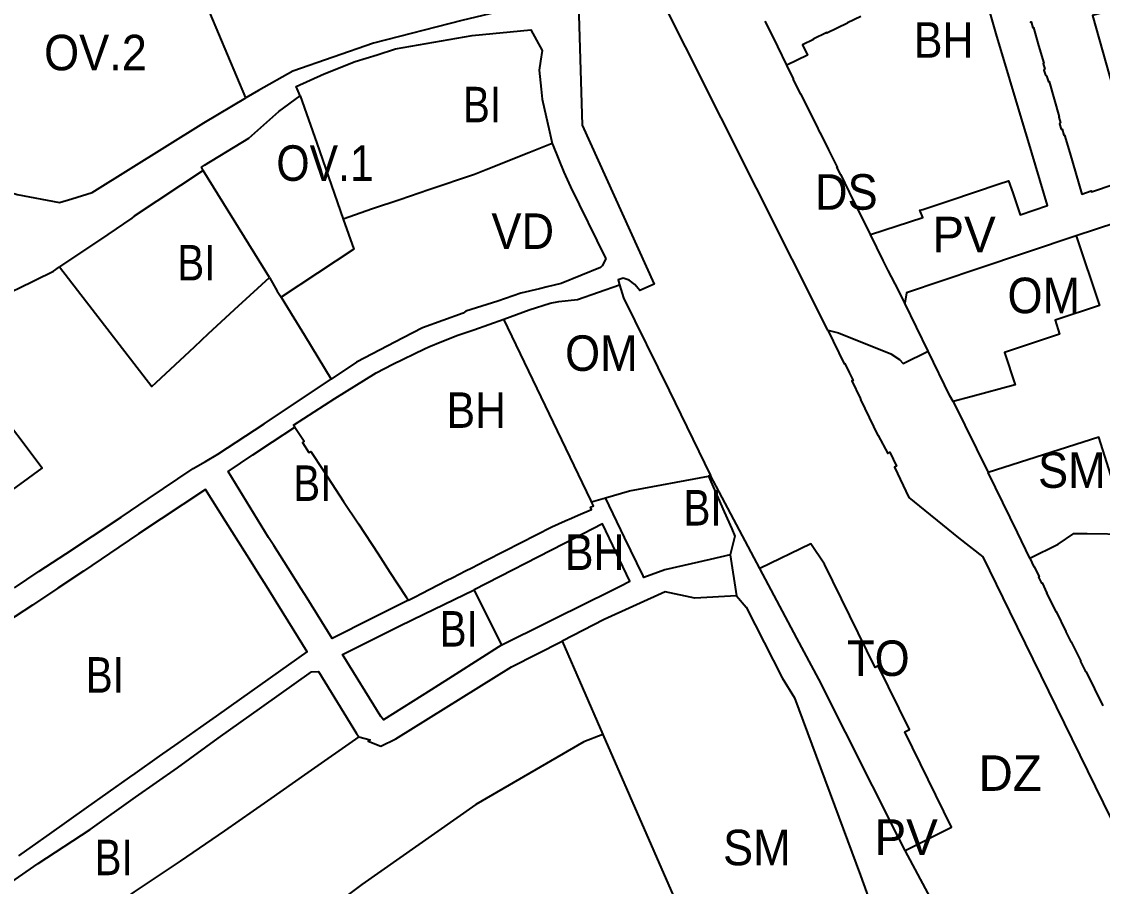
# Model space of a CAD drawing. Extents: x -650451 to -642268, y -1075216 to -1066610.
# Drawn here: x -648055.9 to -647599.3, y -1071003.9 to -1070638.7 of the extents above; entities that cross this region are included whole.
import ezdxf

# ---------------------------------------------------------------- set-up
doc = ezdxf.new("R2010")
doc.units = 0
doc.header["$LTSCALE"] = 6
doc.layers.add('1', color=7, linetype='Continuous', lineweight=35)
doc.layers.add('2', color=7, linetype='Continuous')
doc.layers.add('3', color=7, linetype='Continuous')

msp = doc.modelspace()

# ---------------------------------------------------------------- linework, layer by layer
at = {"layer": '1'}
for p, q in [((-647951.11, -1070746.78), (-647979.17, -1070701.65)), ((-647672.865, -1070777.891), (-647682.67, -1070757.67)), ((-647662.26, -1070799.23), (-647647.571, -1070829.133)), ((-647764.84, -1070830.47), (-647765.72, -1070830.64)), ((-647815.09, -1070841.49), (-647809.12, -1070839.89)), ((-647756.45, -1070863.95), (-647753.81, -1070881.3)), ((-647852.97, -1070901.96), (-647864.71, -1070878.74)), ((-647827.527, -1070900.351), (-647810.243, -1070939.825)), ((-647810.243, -1070939.825), (-647765.408, -1071042.223))]:
    msp.add_line(p, q, dxfattribs=at)
for points in [[(-647884.92, -1070338.99), (-647886.21, -1070365.54), (-647887.07, -1070416.41), (-647878.96, -1070462.33), (-647864.39, -1070538.27), (-647847.43, -1070592.87), (-647838.01, -1070623.65), (-647823.823, -1070616.697), (-647819.04, -1070625.82), (-647820.78, -1070626.64), (-647818.97, -1070682.49), (-647788.61, -1070749.59), (-647794.72, -1070752.32), (-647796.81, -1070749.77), (-647799.17, -1070747.87), (-647801.72, -1070747.13), (-647803.86, -1070747.73), (-647803.27, -1070749.84)], [(-647879.89, -1070513.91), (-647874.57, -1070543.74), (-647874.57, -1070544.88), (-647875.18, -1070545.86), (-647875.88, -1070546.28), (-647875.79, -1070546.93), (-647875.64, -1070547.77), (-647874.97, -1070551.71), (-647874.48, -1070554.33), (-647872.39, -1070554.51), (-647871.15, -1070555.05), (-647870.17, -1070556.03), (-647869.25, -1070556.63), (-647848.14, -1070626.09), (-647847.8, -1070628.31), (-647849.67, -1070630.94), (-647855.03, -1070634.7), (-647869.87, -1070638.25), (-647907.21, -1070647.84), (-647941.33, -1070659.67), (-647955.81, -1070667.9), (-647961.11, -1070670.91)], [(-647961.11, -1070670.91), (-647980.2, -1070625.7), (-647984.03, -1070585.46)], [(-647715.3, -1070769.09), (-647790.4, -1070619.27), (-647792.4, -1070613.99)], [(-647697.19, -1070728.71), (-647675.18, -1070721.4), (-647676.32, -1070718.44), (-647675.08, -1070718.03), (-647663.76, -1070714.27), (-647642.89, -1070707.32), (-647638.89, -1070706.02), (-647637.16, -1070711.08), (-647633.97, -1070720.39), (-647622.42, -1070716.46), (-647630.62, -1070688.97), (-647632.63, -1070682.45), (-647644.14, -1070643.84), (-647648.1, -1070630.11)], [(-647701.31, -1070636.54), (-647706.97, -1070639.28), (-647706.92, -1070639.43), (-647711.25, -1070641.47), (-647715.62, -1070643.56), (-647715.68, -1070643.41), (-647721.4, -1070646.19), (-647721.35, -1070646.32), (-647725.98, -1070648.59), (-647723.91, -1070652.88), (-647732.61, -1070657.08)], [(-647598.3, -1070634.71), (-647603.37, -1070636.19), (-647593.48, -1070671.67), (-647553.95, -1070659.71)], [(-647732.61, -1070657.08), (-647736.4, -1070649.31), (-647740.59, -1070640.7), (-647741.7, -1070638.5)], [(-647629.93, -1070638.72), (-647629.59, -1070638.94), (-647629.41, -1070638.87), (-647628.67, -1070641.34), (-647628.41, -1070641.25), (-647626.19, -1070648.79), (-647624.04, -1070656.27), (-647624.32, -1070656.37), (-647623.61, -1070658.84), (-647623.84, -1070658.92), (-647623.94, -1070659.3), (-647623.36, -1070661.41), (-647623.03, -1070661.67), (-647622.83, -1070661.6), (-647622.06, -1070664.18), (-647621.78, -1070664.08), (-647619.6, -1070671.54), (-647617.45, -1070678.98), (-647617.73, -1070679.09), (-647617.01, -1070681.56), (-647617.24, -1070681.65), (-647617.37, -1070681.97), (-647616.72, -1070684.14), (-647616.47, -1070684.33), (-647616.22, -1070684.23), (-647615.48, -1070686.75), (-647615.21, -1070686.65), (-647612.98, -1070694.17), (-647607.96, -1070711.55), (-647604.05, -1070710.22), (-647603.9, -1070710.66), (-647594.26, -1070707.45)], [(-647938.2, -1070670.05), (-647939.82, -1070666.19), (-647928.03, -1070660.74), (-647914.94, -1070655.62), (-647905.7, -1070652.72), (-647897.91, -1070650.27), (-647865.49, -1070644.56), (-647840.71, -1070642.28), (-647835.98, -1070650.97), (-647836.7, -1070655.5), (-647837.27, -1070659.18), (-647836.41, -1070667.24), (-647835.96, -1070671.43), (-647832.86, -1070685.08), (-647831.69, -1070690.25)], [(-647697.19, -1070728.71), (-647706.03, -1070710.73), (-647709.63, -1070703.43), (-647709.81, -1070703.52), (-647711.41, -1070700.27), (-647711.22, -1070700.17), (-647714.83, -1070692.9), (-647718.4, -1070685.67), (-647718.46, -1070685.698), (-647720.094, -1070682.395), (-647720.01, -1070682.36), (-647723.69, -1070675.2), (-647726.54, -1070669.36), (-647726.67, -1070669.43), (-647729.88, -1070663.01), (-647729.74, -1070662.95), (-647732.61, -1070657.08)], [(-648098.637, -1070659.682), (-648089.82, -1070676.22), (-648073.56, -1070706.71), (-648073.25, -1070706.87), (-648062.7, -1070710.16), (-648057.8, -1070711.7), (-648039.79, -1070715.13), (-648034.59, -1070713.53), (-648034.6, -1070713.538), (-648026.1, -1070710.93), (-647978.924, -1070681.443), (-647961.11, -1070670.91)], [(-647979.17, -1070701.65), (-647979.9, -1070700.21), (-647978.63, -1070699.43), (-647959.83, -1070687.95), (-647947.15, -1070676.73), (-647938.2, -1070670.05)], [(-647938.2, -1070670.05), (-647931.07, -1070690.12), (-647920.01, -1070722.11)], [(-647831.69, -1070690.25), (-647831.31, -1070691.17), (-647826.73, -1070702.37), (-647824.01, -1070708.56), (-647809.17, -1070738.64), (-647809.02, -1070738.94), (-647810.66, -1070741.93), (-647811.35, -1070742.52), (-647827.9, -1070749.31), (-647833.82, -1070750.74), (-647837.11, -1070751.54), (-647844.91, -1070753.48), (-647854.65, -1070756.77), (-647868.14, -1070761.03), (-647869.29, -1070761.92), (-647886.51, -1070768.03), (-647894.71, -1070772.31), (-647914.43, -1070782.61), (-647925.06, -1070789.71)], [(-647831.69, -1070690.25), (-647835.87, -1070691.91), (-647841.59, -1070694.17), (-647859.53, -1070701.28), (-647864.53, -1070703.26), (-647883.85, -1070709.85), (-647896.03, -1070714.02), (-647907.68, -1070717.84), (-647920.01, -1070722.11)], [(-647979.17, -1070701.65), (-648008.28, -1070720.96), (-648009.29, -1070721.79), (-648019.49, -1070728.65), (-648039.82, -1070742.33)], [(-647920.01, -1070722.11), (-647915.45, -1070734.9), (-647946.27, -1070755.09)], [(-647583.221, -1070720.205), (-647583.22, -1070720.2), (-647593.6, -1070723.68), (-647610.33, -1070729.281)], [(-647682.67, -1070757.67), (-647685.41, -1070752.2), (-647689.79, -1070743.79), (-647691.89, -1070739.6), (-647697.19, -1070728.71)], [(-647610.33, -1070729.281), (-647651.82, -1070743.17), (-647682.08, -1070753.29), (-647682.67, -1070757.67)], [(-647610.33, -1070729.281), (-647600.53, -1070758.65), (-647619.2, -1070764.85), (-647617.36, -1070770.69), (-647619.12, -1070771.28), (-647640.66, -1070778.47), (-647636.12, -1070792.13), (-647654.89, -1070797.23), (-647662.26, -1070799.23)], [(-648089.27, -1070771.57), (-648074.13, -1070762.04), (-648069.29, -1070758.81), (-648066.27, -1070756.8), (-648065.81, -1070756.49), (-648060.07, -1070752.67), (-648057.56, -1070751.63), (-648042.44, -1070744.09), (-648039.82, -1070742.33)], [(-648039.82, -1070742.33), (-648000.85, -1070792.88), (-647999.06, -1070791.2), (-647982.89, -1070776.05), (-647976.97, -1070770.51), (-647964.21, -1070758.77), (-647951.11, -1070746.78)], [(-647951.11, -1070746.78), (-647947.83, -1070752.55), (-647946.27, -1070755.09)], [(-647852.16, -1070764.35), (-647841.37, -1070760.42), (-647832.6, -1070757.6), (-647828.92, -1070756.92), (-647821.05, -1070756.07), (-647803.27, -1070749.84)], [(-647803.27, -1070749.84), (-647801.54, -1070755.44), (-647782.32, -1070794.55), (-647764.84, -1070830.47)], [(-647946.27, -1070755.09), (-647940.89, -1070763.87), (-647936.39, -1070771.22), (-647925.06, -1070789.71)], [(-647940.38, -1070810.06), (-647941.01, -1070809.16), (-647923.51, -1070797.95), (-647906.13, -1070787.1), (-647898.99, -1070783.35), (-647885.65, -1070776.94), (-647883.78, -1070776.11), (-647878.36, -1070773.89), (-647871.54, -1070771.23), (-647865.7, -1070769.15), (-647864.85, -1070768.85), (-647852.16, -1070764.35)], [(-647815.09, -1070841.49), (-647815.42, -1070840.8), (-647831.15, -1070808.09), (-647832.89, -1070804.46), (-647852.16, -1070764.35)], [(-648125.2, -1070794.79), (-648083.65, -1070854.89), (-648074.41, -1070849.79), (-648072.59, -1070848.79), (-648065.35, -1070844.8), (-648061.52, -1070842.68), (-648063.76, -1070839.49), (-648056.61, -1070834.26), (-648047.17, -1070827.35), (-648089.27, -1070771.57)], [(-647715.3, -1070769.09), (-647710.72, -1070770.23), (-647688.68, -1070779.09), (-647684.98, -1070781.39), (-647683.41, -1070783.12), (-647672.865, -1070777.891)], [(-647715.3, -1070769.09), (-647708.31, -1070783.21), (-647708.04, -1070783.07), (-647706.21, -1070786.87), (-647704.498, -1070790.24), (-647705.06, -1070790.51), (-647701.56, -1070797.79), (-647701.32, -1070798.28), (-647701.41, -1070798.33), (-647694.09, -1070813.56), (-647693.96, -1070813.49), (-647689.95, -1070821.13), (-647689.08, -1070820.64), (-647686.2, -1070826.54), (-647687.12, -1070826.94), (-647681.06, -1070839.75), (-647660.03, -1070856.69), (-647649.83, -1070864.82), (-647638.54, -1070887.82), (-647572.64, -1071022.41), (-647567.83, -1071032.07), (-647565.56, -1071036.69), (-647553.4, -1071061.35), (-647539.817, -1071089.199)], [(-647662.26, -1070799.23), (-647663.71, -1070796.77), (-647672.865, -1070777.891)], [(-648058.9, -1070877.9), (-648048.4, -1070870.83), (-648037.23, -1070863.44), (-648025.98, -1070856), (-648013.79, -1070848.03), (-648002.36, -1070840.34), (-647983.33, -1070827.5), (-647978.2, -1070824.47), (-647973.03, -1070821.42), (-647953.45, -1070808.54), (-647939.28, -1070799.12), (-647925.06, -1070789.71)], [(-647892.43, -1070883.1), (-647907.6, -1070890.67), (-647924.61, -1070899.26), (-647935.21, -1070882.28), (-647937.73, -1070878.28), (-647943.2, -1070869.58), (-647949.31, -1070859.95), (-647951.51, -1070856.55), (-647968.61, -1070828.72), (-647958.2, -1070821.7), (-647949.84, -1070816.25), (-647940.38, -1070810.06)], [(-647940.38, -1070810.06), (-647936.51, -1070815.98), (-647937.23, -1070816.43), (-647934.54, -1070820.72), (-647933.73, -1070820.24), (-647928.5, -1070828.24), (-647923.26, -1070836.26), (-647919.94, -1070841.35), (-647913.48, -1070850.9), (-647905.25, -1070863.56), (-647900.3, -1070871.22), (-647896.99, -1070876.22), (-647893.23, -1070881.89), (-647892.43, -1070883.1)], [(-647588.4, -1070855.25), (-647588.89, -1070851.67), (-647600.8, -1070814.27), (-647647.571, -1070829.133)], [(-647809.12, -1070839.89), (-647799.01, -1070836.93), (-647765.72, -1070830.64)], [(-647765.72, -1070830.64), (-647759.08, -1070845.74), (-647755.87, -1070853.02), (-647754.6, -1070856.11), (-647756.45, -1070863.95)], [(-647682.515, -1070988.758), (-647685.1, -1070983.93), (-647719.06, -1070916.45), (-647728.35, -1070899.11), (-647743.97, -1070869.72), (-647764.84, -1070830.47)], [(-647629.92, -1070865.35), (-647635.09, -1070854.54), (-647647.571, -1070829.133)], [(-648057.03, -1070990.99), (-648048.91, -1070985.24), (-648044.1, -1070981.84), (-648028.51, -1070970.81), (-648010.09, -1070957.8), (-648007.86, -1070956.22), (-647997.6, -1070948.97), (-647989.77, -1070943.44), (-647977.71, -1070934.97), (-647973.51, -1070932.01), (-647962.83, -1070924.47), (-647935.22, -1070904.93), (-647940.69, -1070896.01), (-647948.34, -1070883.81), (-647952.47, -1070877.2), (-647956.4, -1070870.97), (-647958.94, -1070866.95), (-647969.59, -1070849.93), (-647978.24, -1070836.38), (-648006.41, -1070855.1), (-648018.78, -1070863.41), (-648029.74, -1070870.77), (-648040.51, -1070877.96), (-648051.3, -1070885.22), (-648062.26, -1070892.34)], [(-647892.43, -1070883.1), (-647889.65, -1070881.67), (-647886.98, -1070880.31), (-647876.3, -1070874.83), (-647873.63, -1070873.47), (-647868.29, -1070870.73), (-647865.61, -1070869.36), (-647862.94, -1070867.99), (-647860.08, -1070866.53), (-647851.73, -1070862.25), (-647831.91, -1070852.1), (-647829.09, -1070850.87), (-647826.24, -1070849.63), (-647823.49, -1070848.43), (-647820.7, -1070847.22), (-647815.06, -1070844.76), (-647815.49, -1070843.78), (-647814.26, -1070843.22), (-647815.09, -1070841.49)], [(-647756.45, -1070863.95), (-647765.03, -1070865.9), (-647784.05, -1070870.23), (-647792.95, -1070873.45), (-647793.27, -1070872.79), (-647801.09, -1070856.56), (-647809.12, -1070839.89)], [(-647852.97, -1070901.96), (-647814.89, -1070883.09), (-647814.06, -1070882.68), (-647811.38, -1070881.34), (-647803.05, -1070877.19), (-647798.85, -1070875.09), (-647810.47, -1070850.9), (-647826.76, -1070859.26), (-647864.71, -1070878.74)], [(-647629.92, -1070865.35), (-647618.01, -1070859.42), (-647611.3, -1070854.9), (-647605.64, -1070854.99), (-647588.4, -1070855.25)], [(-647682.515, -1070988.758), (-647662.998, -1070979.004), (-647682.683, -1070938.651), (-647680.82, -1070937.75), (-647694.05, -1070910.83), (-647695.32, -1070911.5), (-647716.69, -1070867.87), (-647722.46, -1070859.31), (-647743.97, -1070869.72)], [(-647629.92, -1070865.35), (-647628.26, -1070869.03), (-647628.13, -1070868.96), (-647626.17, -1070872.82), (-647625.96, -1070873.26), (-647626.22, -1070873.4), (-647625.03, -1070875.88), (-647624.74, -1070875.73), (-647622.66, -1070880.07), (-647622.81, -1070880.15), (-647621.04, -1070883.61), (-647618.92, -1070887.94), (-647618.79, -1070887.87), (-647614.65, -1070896.31), (-647614.61, -1070896.41), (-647614.75, -1070896.48), (-647612.62, -1070900.73), (-647612.49, -1070900.66), (-647608.41, -1070908.85), (-647608.55, -1070908.92), (-647606.46, -1070913.18), (-647606.33, -1070913.11), (-647606.18, -1070913.28), (-647599.03, -1070927.71)], [(-647852.97, -1070901.96), (-647872.46, -1070914.35), (-647882.89, -1070920.97), (-647902.94, -1070933.67), (-647904.09, -1070932.21), (-647920.31, -1070906.01), (-647896.01, -1070893.88), (-647885.93, -1070889), (-647864.71, -1070878.74)], [(-647753.81, -1070881.3), (-647771.47, -1070882.27), (-647783.95, -1070879.58), (-647809.74, -1070891.31), (-647827.527, -1070900.351)], [(-647753.81, -1070881.3), (-647749.75, -1070886.1), (-647734.48, -1070915.94), (-647729.27, -1070924.35), (-647701.45, -1070999.4), (-647694.54, -1071018.549), (-647718, -1071022), (-647736, -1071028), (-647750, -1071034), (-647765.408, -1071042.223)], [(-647913.45, -1070940.79), (-647908.63, -1070942.1), (-647909.42, -1070942.63), (-647904.13, -1070944.78), (-647897.76, -1070941.62), (-647848.89, -1070911.21), (-647827.527, -1070900.351)], [(-648092.72, -1071025.89), (-648081.31, -1071017.99), (-648077.63, -1071015.44), (-648063.68, -1071004.56), (-648048.88, -1070994.33), (-648026.92, -1070979.95), (-648007.74, -1070966.29), (-647989.98, -1070953.85), (-647972.8, -1070941.37), (-647954.37, -1070928.31), (-647933.41, -1070913.4), (-647930.48, -1070913.2), (-647914.34, -1070939.36), (-647913.45, -1070940.79)], [(-647913.45, -1070940.79), (-647934.9, -1070955.87), (-647952.01, -1070967.82), (-647970.19, -1070980.45), (-647988.81, -1070993.27), (-648008.34, -1071006.32), (-648030.24, -1071021.91), (-648044.82, -1071032.25), (-648051.48, -1071036.97), (-648062.53, -1071044.59), (-648074.121, -1071052.749)], [(-647810.243, -1070939.825), (-647818.33, -1070942.91), (-647864.03, -1070969.3), (-647912.11, -1071003.11), (-647925.216, -1071013.033), (-647930.7, -1071017.18), (-647977.41, -1071049.74), (-648001.922, -1071067.83), (-647875.939, -1071221.104)], [(-647640.727, -1071095.819), (-647648.106, -1071065.551), (-647654.747, -1071047.095), (-647657.699, -1071038.232), (-647659.01, -1071032.66), (-647682.515, -1070988.758)]]:
    msp.add_lwpolyline(points, dxfattribs=at)

# ---------------------------------------------------------------- texts
at = {"layer": '2'}
for s, width, p in [('BH', 0.9, (-647678.861, -1070653.995)), ('OV.2', 0.95, (-648046.37, -1070659.303)), ('BI', 0.85, (-647869.417, -1070681.282)), ('OV.1', 0.9, (-647948.24, -1070705.986)), ('DS', 0.95, (-647720.675, -1070718.182)), ('VD', 0.95, (-647857.375, -1070734.747)), ('OM', 0.95, (-647639.34, -1070761.88)), ('OM', 0.95, (-647826.28, -1070786.24)), ('BH', 0.9, (-647876.304, -1070810.321)), ('BI', 0.85, (-647941.12, -1070841.178)), ('BI', 0.85, (-647776.222, -1070851.553)), ('BH', 0.9, (-647826.295, -1070870.332)), ('BI', 0.85, (-647879.237, -1070902.69)), ('TO', 0.95, (-647707.119, -1070915.089)), ('BI', 0.85, (-648028.756, -1070922.143)), ('BI', 0.85, (-648025.05, -1070999.219))]:
    msp.add_text(s, height=15, dxfattribs=dict(at, width=width)).set_placement(p)
for s, p in [('PV', (-647671.058, -1070736.14)), ('DZ', (-647651.582, -1070963.608))]:
    msp.add_text(s, height=15, dxfattribs=at).set_placement(p)
at = {"layer": '3'}
for s, width, p in [('BI', 0.85, (-647990.092, -1070748.061)), ('SM', 0.95, (-647626.45, -1070835.638)), ('SM', 0.95, (-647759.526, -1070995.032))]:
    msp.add_text(s, height=15, dxfattribs=dict(at, width=width)).set_placement(p)
msp.add_text('PV', height=15, dxfattribs=at).set_placement((-647695.526, -1070990.635))

doc.saveas('drawing.dxf')
